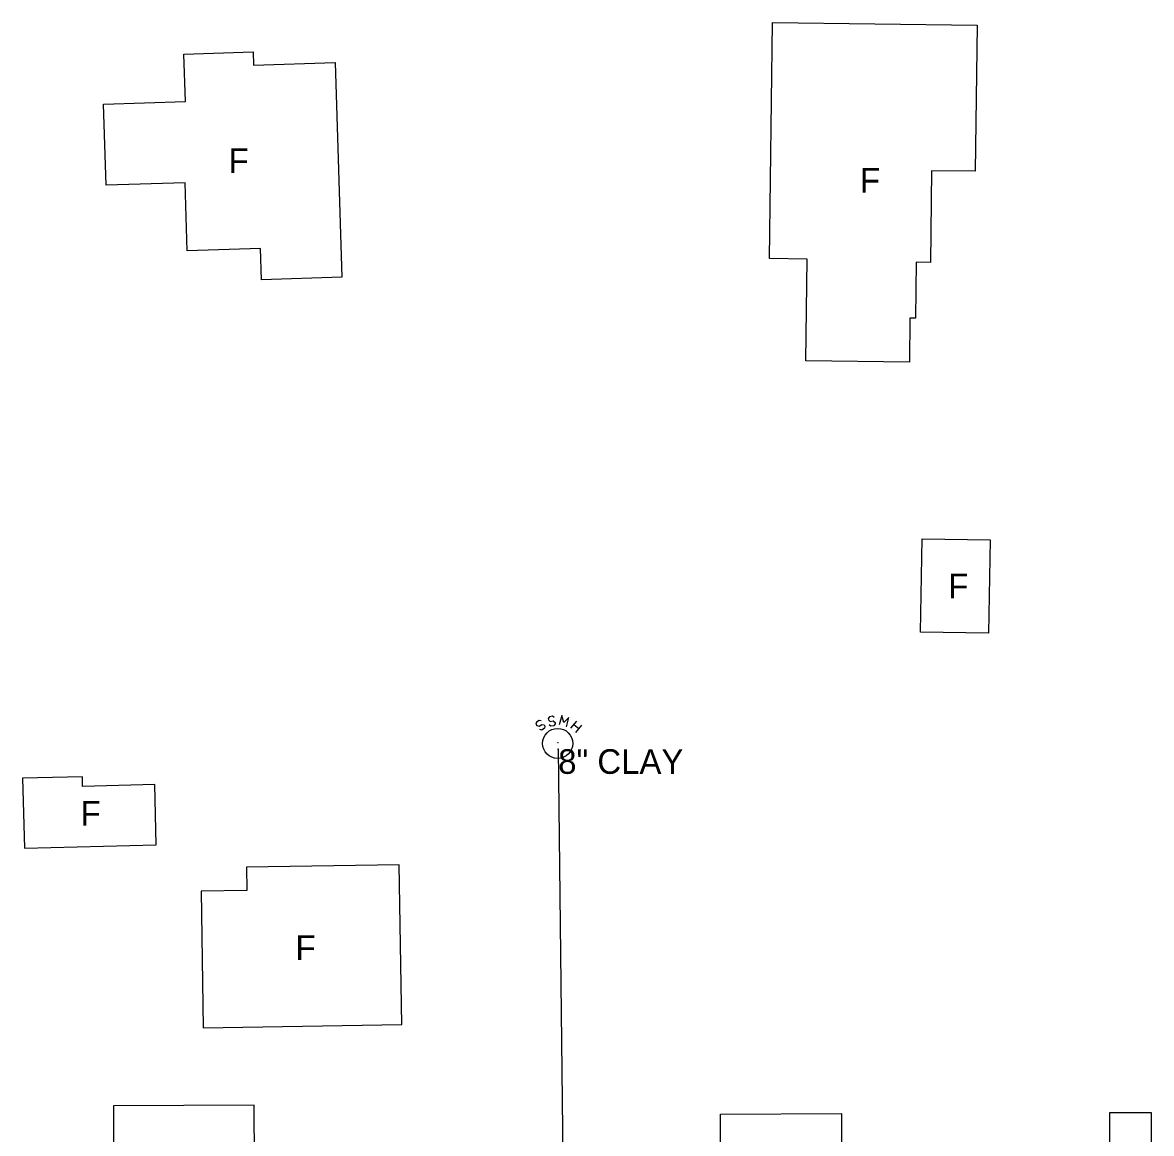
# Model space of a CAD drawing. Extents: x 1304270 to 1306561, y 1876019 to 1876752.
# Drawn here: x 1306122.1 to 1306351.3, y 1876526.4 to 1876752 of the extents above; entities that cross this region are included whole.
import ezdxf

# ---------------------------------------------------------------- set-up
doc = ezdxf.new("R2010")
doc.units = 0
for name, color, linetype in [('S_BUILDING', 7, 'Continuous'), ('S_BUILDING_ANNOT', 7, 'Continuous'), ('S_MANHOLE', 7, 'Continuous'), ('S_SANITARY_SEWER', 7, 'Continuous'), ('S_SANITARY_SEWER_ANNOT', 7, 'Continuous'), ('S_UTL_PT_SYM', 7, 'Continuous')]:
    doc.layers.add(name, color=color, linetype=linetype)

msp = doc.modelspace()

# ---------------------------------------------------------------- linework, layer by layer
at = {"layer": 'S_BUILDING'}
for points in [[(1306273.73, 1876704.05), (1306274.33, 1876751.96), (1306315.88, 1876751.44), (1306315.51, 1876721.77), (1306306.62, 1876721.89), (1306306.39, 1876703.28), (1306303.49, 1876703.31), (1306303.35, 1876691.97), (1306302.24, 1876691.98), (1306302.13, 1876683), (1306281.11, 1876683.26), (1306281.37, 1876703.96)], [(1306185.5, 1876743.85), (1306186.9, 1876700.29), (1306170.59, 1876699.76), (1306170.39, 1876706.08), (1306155.48, 1876705.6), (1306155.04, 1876719.45), (1306139.04, 1876718.93), (1306138.51, 1876735.42), (1306155.13, 1876735.95), (1306154.83, 1876745.58), (1306168.89, 1876746.04), (1306168.97, 1876743.32)], [(1306304.39, 1876628.2), (1306304.7, 1876647.18), (1306318.5, 1876646.95), (1306318.19, 1876627.98)], [(1306122.44, 1876584.33), (1306149.21, 1876585.05), (1306148.88, 1876597.27), (1306134.25, 1876596.88), (1306134.19, 1876598.85), (1306122.05, 1876598.53)], [(1306199.04, 1876548.55), (1306198.52, 1876580.99), (1306167.51, 1876580.49), (1306167.58, 1876575.77), (1306158.29, 1876575.62), (1306158.73, 1876547.9)], [(1306169.41, 1876474.94), (1306169.05, 1876532.19), (1306140.49, 1876532.01), (1306140.61, 1876513.24), (1306124.53, 1876513.14), (1306124.77, 1876474.66)], [(1306264.09, 1876452.02), (1306263.78, 1876530.37), (1306288.35, 1876530.47), (1306288.67, 1876452.12)], [(1306342.76, 1876530.65), (1306342.73, 1876512.09), (1306351.24, 1876512.07), (1306351.28, 1876530.63)]]:
    msp.add_lwpolyline(points, close=True, dxfattribs=at)
at = {"layer": 'S_MANHOLE'}
for p, q in [((1306226.39, 1876609.92), (1306226.31, 1876609.53)), ((1306226.31, 1876609.53), (1306226.5, 1876609.26)), ((1306226.93, 1876610.3), (1306226.39, 1876609.92)), ((1306226.5, 1876609.26), (1306226.93, 1876609.14)), ((1306227.35, 1876610.23), (1306226.93, 1876610.3)), ((1306226.93, 1876609.14), (1306227.47, 1876609.49)), ((1306227.47, 1876609.49), (1306227.94, 1876609.41)), ((1306227.94, 1876609.41), (1306228.09, 1876609.14)), ((1306233.36, 1876608.68), (1306234.6, 1876610.15)), ((1306234.02, 1876609.45), (1306234.99, 1876608.64)), ((1306235.57, 1876609.34), (1306234.33, 1876607.86)), ((1306227.47, 1876608.33), (1306227.08, 1876608.41)), ((1306228.01, 1876608.72), (1306227.47, 1876608.33)), ((1306228.09, 1876609.14), (1306228.01, 1876608.72))]:
    msp.add_line(p, q, dxfattribs=at)
for points in [[(1306230.03, 1876610.85), (1306229.68, 1876611.12), (1306229.02, 1876611.04), (1306228.79, 1876610.69), (1306228.83, 1876610.38), (1306229.18, 1876610.07), (1306229.8, 1876610.19), (1306230.18, 1876609.88), (1306230.22, 1876609.57), (1306229.95, 1876609.18), (1306229.33, 1876609.1), (1306228.98, 1876609.37)], [(1306232.47, 1876608.99), (1306233.01, 1876610.85), (1306231.97, 1876609.84), (1306231.58, 1876611.27), (1306231.04, 1876609.41)]]:
    msp.add_lwpolyline(points, dxfattribs=at)
msp.add_circle((1306230.71, 1876605.61), 3.05, dxfattribs=at)
at = {"layer": 'S_SANITARY_SEWER'}
msp.add_line((1306230.82, 1876604.44), (1306232.63, 1876441.82), dxfattribs=at)
at = {"layer": 'S_UTL_PT_SYM'}
for points in [[(1306230.76, 1876605.77), (1306230.76, 1876605.82), (1306230.76, 1876605.77), (1306230.71, 1876605.77), (1306230.76, 1876605.77), (1306230.76, 1876605.72), (1306230.76, 1876605.77), (1306230.81, 1876605.77)], [(1306230.82, 1876604.44), (1306230.82, 1876604.49), (1306230.82, 1876604.44), (1306230.77, 1876604.44), (1306230.82, 1876604.44), (1306230.82, 1876604.39), (1306230.82, 1876604.44), (1306230.87, 1876604.44)]]:
    msp.add_lwpolyline(points, dxfattribs=at)

# ---------------------------------------------------------------- texts
at = {"layer": 'S_BUILDING_ANNOT'}
for p in [(1306163.89, 1876721.41), (1306292.11, 1876717.46), (1306310.01, 1876635.08), (1306133.84, 1876588.93), (1306177.46, 1876561.66)]:
    msp.add_text('F', height=5, dxfattribs=at).set_placement(p)
at = {"layer": 'S_SANITARY_SEWER_ANNOT'}
msp.add_text('8" CLAY', height=5, dxfattribs=at).set_placement((1306230.82, 1876599.44))

doc.saveas('drawing.dxf')
